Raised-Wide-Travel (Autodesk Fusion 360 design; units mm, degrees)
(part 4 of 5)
work_plane "WorkPlane10" AlongDistance -1.3 ExtraOffset 0
sketch "Upper clamp screw clearance" plane through (0, -1.3, 0) normal (0, 1, 0) x axis (1, 0, 0)
  circle C1 centre (44.5, -73) radius 1.7
extrude "Extrude10" cut sketch "Upper clamp screw clearance" along normal blind 6.4
work_plane "WorkPlane11" AlongDistance 5 ExtraOffset 0
sketch "Upper clamp head recess" plane through (0, 5, 0) normal (0, 1, 0) x axis (1, 0, 0)
  circle C1 centre (44.5, -73) radius 3.1
extrude "Extrude11" cut sketch "Upper clamp head recess" along normal blind 30
work_plane "WorkPlane1" AlongDistance -7 ExtraOffset 0
sketch "G01 upper clamp M3x12" plane through (0, -7, 0) normal (0, 1, 0) x axis (1, 0, 0)
  circle C1 centre (44.5, -73) radius 1.5
extrude "Extrude1" new body sketch "G01 upper clamp M3x12" along normal blind 12 bodies "HARDWARE G01 upper clamp M3x12"
work_plane "WorkPlane2" AlongDistance 5 ExtraOffset 0
sketch "Button head" plane through (0, 5, 0) normal (0, 1, 0) x axis (1, 0, 0)
  circle C1 centre (44.5, -73) radius 2.75
extrude "Extrude2" add sketch "Button head" along normal blind 3
ground "Unpin124"
ground "Unpin125"
ground "Unpin126"
ground "Unpin127"
ground "Unpin130"
ground "Unpin131"
ground "Unpin132"
ground "Unpin133"
ground "Unpin134"
ground "Unpin135"
ground "Unpin136"
ground "Unpin141"
ground "Unpin142"
ground "Unpin143"
ground "Unpin144"
ground "Unpin145"
ground "Unpin146"
ground "Unpin147"
ground "Unpin148"
ground "Unpin149"
ground "Unpin150"
ground "Unpin151"
ground "Unpin152"
position "Position2"
work_plane "WorkPlane86" AlongDistance 24 ExtraOffset 0
sketch "Outer lower sensor support clear of cam" plane through (24, 0, 0) normal (1, 0, 0) x axis (0, 0, -1)
  line L1 (-4, -49) -> (-4, -62)
  line L2 (-35, -49) -> (-4, -49)
  line L3 (-35, -62) -> (-35, -49)
  line L4 (-4, -62) -> (-35, -62)
extrude "Extrude86" add sketch "Outer lower sensor support clear of cam" along normal blind 10
work_plane "WorkPlane87" AlongDistance 24 ExtraOffset 0
sketch "Outer lower M3 insert" plane through (24, 0, 0) normal (1, 0, 0) x axis (0, 0, -1)
  circle C1 centre (-19.85, -55) radius 2
extrude "Extrude87" cut sketch "Outer lower M3 insert" along normal blind 6.8
work_plane "WorkPlane88" AlongDistance 30.7 ExtraOffset 0
sketch "Outer lower screw clearance" plane through (30.7, 0, 0) normal (1, 0, 0) x axis (0, 0, -1)
  circle C1 centre (-19.85, -55) radius 1.7
extrude "Extrude88" cut sketch "Outer lower screw clearance" along normal blind 3.4
work_plane "WorkPlane89" AlongDistance 24 ExtraOffset 0
sketch "Outer lower sensor support clear of cam (1)" plane through (24, 0, 0) normal (1, 0, 0) x axis (0, 0, -1)
  line L1 (-4, 62) -> (-4, 49)
  line L2 (-35, 62) -> (-4, 62)
  line L3 (-35, 49) -> (-35, 62)
  line L4 (-4, 49) -> (-35, 49)
extrude "Extrude89" add sketch "Outer lower sensor support clear of cam (1)" along normal blind 10
work_plane "WorkPlane90" AlongDistance 24 ExtraOffset 0
sketch "Outer lower M3 insert (1)" plane through (24, 0, 0) normal (1, 0, 0) x axis (0, 0, -1)
  circle C1 centre (-19.85, 55) radius 2
extrude "Extrude90" cut sketch "Outer lower M3 insert (1)" along normal blind 6.8
work_plane "WorkPlane91" AlongDistance 30.7 ExtraOffset 0
sketch "Outer lower screw clearance (1)" plane through (30.7, 0, 0) normal (1, 0, 0) x axis (0, 0, -1)
  circle C1 centre (-19.85, 55) radius 1.7
extrude "Extrude91" cut sketch "Outer lower screw clearance (1)" along normal blind 3.4
work_plane "WorkPlane92" AlongDistance 23.9 ExtraOffset 0
sketch "Potentiometer body and lead clearance (1)" plane through (23.9, 0, 0) normal (1, 0, 0) x axis (0, 0, -1)
  line L1 (-8.5, 8) -> (-8.5, -8)
  line L2 (-31.2, 8) -> (-8.5, 8)
  line L3 (-31.2, -8) -> (-31.2, 8)
  line L4 (-8.5, -8) -> (-31.2, -8)
extrude "Extrude92" cut sketch "Potentiometer body and lead clearance (1)" along normal blind 10.2
work_plane "WorkPlane1" AlongDistance 34 ExtraOffset 0
sketch "Flat lower sensor panel" plane through (34, 0, 0) normal (1, 0, 0) x axis (0, 0, -1)
  line L1 (-4, 62) -> (-4, -62)
  line L2 (-34, 62) -> (-4, 62)
  line L3 (-34, -62) -> (-34, 62)
  line L4 (-4, -62) -> (-34, -62)
extrude "Extrude1" new body sketch "Flat lower sensor panel" along normal blind 3 bodies "G03R Lower removable potentiometer panel"
work_plane "WorkPlane2" AlongDistance 33.9 ExtraOffset 0
sketch "Sensor bushing clearance" plane through (33.9, 0, 0) normal (1, 0, 0) x axis (0, 0, -1)
  circle C1 centre (-19.85, 0) radius 3.6
extrude "Extrude2" cut sketch "Sensor bushing clearance" along normal blind 3.2
work_plane "WorkPlane3" AlongDistance 33.9 ExtraOffset 0
sketch "Radial mesh adjustment slot" plane through (33.9, 0, 0) normal (1, 0, 0) x axis (0, 0, -1)
  line L1 (-16.95, -53.3) -> (-16.95, -56.7)
  line L2 (-22.75, -53.3) -> (-16.95, -53.3)
  line L3 (-22.75, -56.7) -> (-22.75, -53.3)
  line L4 (-16.95, -56.7) -> (-22.75, -56.7)
extrude "Extrude3" cut sketch "Radial mesh adjustment slot" along normal blind 3.2
work_plane "WorkPlane1" AlongDistance 25 ExtraOffset 0
sketch "Lower panel M3x12 -55" plane through (25, 0, 0) normal (1, 0, 0) x axis (0, 0, -1)
  circle C1 centre (-19.85, -55) radius 1.5
extrude "Extrude1" new body sketch "Lower panel M3x12 -55" along normal blind 12 bodies "HARDWARE Lower panel M3x12 -55"
work_plane "WorkPlane2" AlongDistance 37 ExtraOffset 0
sketch "Button head" plane through (37, 0, 0) normal (1, 0, 0) x axis (0, 0, -1)
  circle C1 centre (-19.85, -55) radius 2.75
extrude "Extrude2" add sketch "Button head" along normal blind 3
work_plane "WorkPlane4" AlongDistance 33.9 ExtraOffset 0
sketch "Radial mesh adjustment slot (1)" plane through (33.9, 0, 0) normal (1, 0, 0) x axis (0, 0, -1)
  line L1 (-16.95, 56.7) -> (-16.95, 53.3)
  line L2 (-22.75, 56.7) -> (-16.95, 56.7)
  line L3 (-22.75, 53.3) -> (-22.75, 56.7)
  line L4 (-16.95, 53.3) -> (-22.75, 53.3)
extrude "Extrude4" cut sketch "Radial mesh adjustment slot (1)" along normal blind 3.2
work_plane "WorkPlane1" AlongDistance 25 ExtraOffset 0
sketch "Lower panel M3x12 55" plane through (25, 0, 0) normal (1, 0, 0) x axis (0, 0, -1)
  circle C1 centre (-19.85, 55) radius 1.5
extrude "Extrude1" new body sketch "Lower panel M3x12 55" along normal blind 12 bodies "HARDWARE Lower panel M3x12 55"
work_plane "WorkPlane2" AlongDistance 37 ExtraOffset 0
sketch "Button head" plane through (37, 0, 0) normal (1, 0, 0) x axis (0, 0, -1)
  circle C1 centre (-19.85, 55) radius 2.75
extrude "Extrude2" add sketch "Button head" along normal blind 3
position "Position3"
work_plane "WorkPlane74" AlongDistance -36 ExtraOffset 0
sketch "Top rail hanging suspension arm" plane through (-36, 0, 0) normal (1, 0, 0) x axis (0, 0, -1)
  line L1 (-33, -74.5) -> (-33, -55)
  line L2 (-102, -74.5) -> (-33, -74.5)
  line L3 (-102, -95) -> (-102, -74.5)
  line L4 (-111, -95) -> (-102, -95)
  line L5 (-111, -65) -> (-111, -95)
  line L6 (-57, -55) -> (-111, -65)
  line L7 (-33, -55) -> (-57, -55)
work_plane "WorkPlane75" AlongDistance 101.9 ExtraOffset 0
sketch "Top-access M5 mounting clearance" plane through (0, 0, 101.9) normal (0, 0, 1) x axis (1, 0, 0)
  circle C1 centre (-30, -85) radius 2.7
work_plane "WorkPlane1" AlongDistance 97 ExtraOffset 0
sketch "Top hanging rail M5x14 (-30, -1)" plane through (0, 0, 97) normal (0, 0, 1) x axis (1, 0, 0)
  circle C1 centre (-30, -85) radius 2.5
extrude "Extrude1" new body sketch "Top hanging rail M5x14 (-30, -1)" along normal blind 14 bodies "HARDWARE Top hanging rail M5x14 (-30, -1)"
work_plane "WorkPlane2" AlongDistance 111 ExtraOffset 0
sketch "Button head" plane through (0, 0, 111) normal (0, 0, 1) x axis (1, 0, 0)
  circle C1 centre (-30, -85) radius 4.25
extrude "Extrude2" add sketch "Button head" along normal blind 5
work_plane "WorkPlane76" AlongDistance -36 ExtraOffset 0
sketch "Top rail hanging suspension arm (1)" plane through (-36, 0, 0) normal (1, 0, 0) x axis (0, 0, -1)
  line L1 (-33, 74.5) -> (-33, 55)
  line L2 (-102, 74.5) -> (-33, 74.5)
  line L3 (-102, 95) -> (-102, 74.5)
  line L4 (-111, 95) -> (-102, 95)
  line L5 (-111, 65) -> (-111, 95)
  line L6 (-57, 55) -> (-111, 65)
  line L7 (-33, 55) -> (-57, 55)
work_plane "WorkPlane77" AlongDistance 101.9 ExtraOffset 0
sketch "Top-access M5 mounting clearance (1)" plane through (0, 0, 101.9) normal (0, 0, 1) x axis (1, 0, 0)
  circle C1 centre (-30, 85) radius 2.7
work_plane "WorkPlane1" AlongDistance 97 ExtraOffset 0
sketch "Top hanging rail M5x14 (-30, 1)" plane through (0, 0, 97) normal (0, 0, 1) x axis (1, 0, 0)
  circle C1 centre (-30, 85) radius 2.5
extrude "Extrude1" new body sketch "Top hanging rail M5x14 (-30, 1)" along normal blind 14 bodies "HARDWARE Top hanging rail M5x14 (-30, 1)"
work_plane "WorkPlane2" AlongDistance 111 ExtraOffset 0
sketch "Button head" plane through (0, 0, 111) normal (0, 0, 1) x axis (1, 0, 0)
  circle C1 centre (-30, 85) radius 4.25
extrude "Extrude2" add sketch "Button head" along normal blind 5
work_plane "WorkPlane93" AlongDistance 24 ExtraOffset 0
sketch "Top rail hanging suspension arm" plane through (24, 0, 0) normal (1, 0, 0) x axis (0, 0, -1)
  line L1 (-33, -74.5) -> (-33, -55)
  line L2 (-102, -74.5) -> (-33, -74.5)
  line L3 (-102, -95) -> (-102, -74.5)
  line L4 (-111, -95) -> (-102, -95)
  line L5 (-111, -65) -> (-111, -95)
  line L6 (-57, -55) -> (-111, -65)
  line L7 (-33, -55) -> (-57, -55)
work_plane "WorkPlane94" AlongDistance 101.9 ExtraOffset 0
sketch "Top-access M5 mounting clearance" plane through (0, 0, 101.9) normal (0, 0, 1) x axis (1, 0, 0)
  circle C1 centre (30, -85) radius 2.7
work_plane "WorkPlane1" AlongDistance 97 ExtraOffset 0
sketch "Top hanging rail M5x14 (30, -1)" plane through (0, 0, 97) normal (0, 0, 1) x axis (1, 0, 0)
  circle C1 centre (30, -85) radius 2.5
extrude "Extrude1" new body sketch "Top hanging rail M5x14 (30, -1)" along normal blind 14 bodies "HARDWARE Top hanging rail M5x14 (30, -1)"
work_plane "WorkPlane2" AlongDistance 111 ExtraOffset 0
sketch "Button head" plane through (0, 0, 111) normal (0, 0, 1) x axis (1, 0, 0)
  circle C1 centre (30, -85) radius 4.25
extrude "Extrude2" add sketch "Button head" along normal blind 5
work_plane "WorkPlane95" AlongDistance 24 ExtraOffset 0
sketch "Top rail hanging suspension arm (1)" plane through (24, 0, 0) normal (1, 0, 0) x axis (0, 0, -1)
  line L1 (-33, 74.5) -> (-33, 55)
  line L2 (-102, 74.5) -> (-33, 74.5)
  line L3 (-102, 95) -> (-102, 74.5)
  line L4 (-111, 95) -> (-102, 95)
  line L5 (-111, 65) -> (-111, 95)
  line L6 (-57, 55) -> (-111, 65)
  line L7 (-33, 55) -> (-57, 55)
work_plane "WorkPlane96" AlongDistance 101.9 ExtraOffset 0
sketch "Top-access M5 mounting clearance (1)" plane through (0, 0, 101.9) normal (0, 0, 1) x axis (1, 0, 0)
  circle C1 centre (30, 85) radius 2.7
work_plane "WorkPlane1" AlongDistance 97 ExtraOffset 0
sketch "Top hanging rail M5x14 (30, 1)" plane through (0, 0, 97) normal (0, 0, 1) x axis (1, 0, 0)
  circle C1 centre (30, 85) radius 2.5
extrude "Extrude1" new body sketch "Top hanging rail M5x14 (30, 1)" along normal blind 14 bodies "HARDWARE Top hanging rail M5x14 (30, 1)"
work_plane "WorkPlane2" AlongDistance 111 ExtraOffset 0
sketch "Button head" plane through (0, 0, 111) normal (0, 0, 1) x axis (1, 0, 0)
  circle C1 centre (30, 85) radius 4.25
extrude "Extrude2" add sketch "Button head" along normal blind 5
work_plane "WorkPlane97" AlongDistance 34 ExtraOffset 0
sketch "Recess seat for removable lower sensor panel" plane through (34, 0, 0) normal (1, 0, 0) x axis (0, 0, -1)
  line L1 (-3.8, 62.2) -> (-3.8, -62.2)
  line L2 (-34.2, 62.2) -> (-3.8, 62.2)
  line L3 (-34.2, -62.2) -> (-34.2, 62.2)
  line L4 (-3.8, -62.2) -> (-34.2, -62.2)
extrude "Extrude97" cut sketch "Recess seat for removable lower sensor panel" along normal blind 2.1
position "Position4"
work_plane "WorkPlane78" AlongDistance -36.1 ExtraOffset 0
sketch "Preserve crossblock screw through suspension arm" plane through (-36.1, 0, 0) normal (1, 0, 0) x axis (0, 0, -1)
  circle C1 centre (-53.5, -62) radius 1.7
work_plane "WorkPlane79" AlongDistance -36.1 ExtraOffset 0
sketch "Preserve crossblock screw through suspension arm (1)" plane through (-36.1, 0, 0) normal (1, 0, 0) x axis (0, 0, -1)
  circle C1 centre (-53.5, -70) radius 1.7
work_plane "WorkPlane98" AlongDistance 23.9 ExtraOffset 0
sketch "Preserve crossblock screw through suspension arm" plane through (23.9, 0, 0) normal (1, 0, 0) x axis (0, 0, -1)
  circle C1 centre (-53.5, -62) radius 1.7
work_plane "WorkPlane99" AlongDistance 23.9 ExtraOffset 0
sketch "Preserve crossblock screw through suspension arm (1)" plane through (23.9, 0, 0) normal (1, 0, 0) x axis (0, 0, -1)
  circle C1 centre (-53.5, -70) radius 1.7
work_plane "WorkPlane80" AlongDistance -36 ExtraOffset 0
sketch "Shorter top rail hanger" plane through (-36, 0, 0) normal (1, 0, 0) x axis (0, 0, -1)
  line L1 (-33, -74.5) -> (-33, -55)
  line L2 (-90, -74.5) -> (-33, -74.5)
  line L3 (-90, -95) -> (-90, -74.5)
  line L4 (-99, -95) -> (-90, -95)
  line L5 (-99, -65) -> (-99, -95)
  line L6 (-57, -55) -> (-99, -65)
  line L7 (-33, -55) -> (-57, -55)
extrude "Extrude80" add sketch "Shorter top rail hanger" along normal blind 12
work_plane "WorkPlane81" AlongDistance 89.9 ExtraOffset 0
sketch "Rail M5 clearance" plane through (0, 0, 89.9) normal (0, 0, 1) x axis (1, 0, 0)
  circle C1 centre (-30, -85) radius 2.7
extrude "Extrude81" cut sketch "Rail M5 clearance" along normal blind 9.2
work_plane "WorkPlane82" AlongDistance -36 ExtraOffset 0
sketch "Shorter top rail hanger (1)" plane through (-36, 0, 0) normal (1, 0, 0) x axis (0, 0, -1)
  line L1 (-33, 74.5) -> (-33, 55)
  line L2 (-90, 74.5) -> (-33, 74.5)
  line L3 (-90, 95) -> (-90, 74.5)
  line L4 (-99, 95) -> (-90, 95)
  line L5 (-99, 65) -> (-99, 95)
  line L6 (-57, 55) -> (-99, 65)
  line L7 (-33, 55) -> (-57, 55)
extrude "Extrude82" add sketch "Shorter top rail hanger (1)" along normal blind 12
work_plane "WorkPlane83" AlongDistance 89.9 ExtraOffset 0
sketch "Rail M5 clearance (1)" plane through (0, 0, 89.9) normal (0, 0, 1) x axis (1, 0, 0)
  circle C1 centre (-30, 85) radius 2.7
extrude "Extrude83" cut sketch "Rail M5 clearance (1)" along normal blind 9.2
work_plane "WorkPlane84" AlongDistance -36.1 ExtraOffset 0
sketch "Restore crossblock passage" plane through (-36.1, 0, 0) normal (1, 0, 0) x axis (0, 0, -1)
  circle C1 centre (-53.5, -62) radius 1.7
extrude "Extrude84" cut sketch "Restore crossblock passage" along normal blind 12.2
work_plane "WorkPlane85" AlongDistance -36.1 ExtraOffset 0
sketch "Restore crossblock passage (1)" plane through (-36.1, 0, 0) normal (1, 0, 0) x axis (0, 0, -1)
  circle C1 centre (-53.5, -70) radius 1.7
extrude "Extrude85" cut sketch "Restore crossblock passage (1)" along normal blind 12.2
work_plane "WorkPlane100" AlongDistance 24 ExtraOffset 0
sketch "Shorter top rail hanger" plane through (24, 0, 0) normal (1, 0, 0) x axis (0, 0, -1)
  line L1 (-33, -74.5) -> (-33, -55)
  line L2 (-90, -74.5) -> (-33, -74.5)
  line L3 (-90, -95) -> (-90, -74.5)
  line L4 (-99, -95) -> (-90, -95)
  line L5 (-99, -65) -> (-99, -95)
  line L6 (-57, -55) -> (-99, -65)
  line L7 (-33, -55) -> (-57, -55)
extrude "Extrude100" add sketch "Shorter top rail hanger" along normal blind 12
work_plane "WorkPlane101" AlongDistance 89.9 ExtraOffset 0
sketch "Rail M5 clearance" plane through (0, 0, 89.9) normal (0, 0, 1) x axis (1, 0, 0)
  circle C1 centre (30, -85) radius 2.7
extrude "Extrude101" cut sketch "Rail M5 clearance" along normal blind 9.2
work_plane "WorkPlane102" AlongDistance 24 ExtraOffset 0
sketch "Shorter top rail hanger (1)" plane through (24, 0, 0) normal (1, 0, 0) x axis (0, 0, -1)
  line L1 (-33, 74.5) -> (-33, 55)
  line L2 (-90, 74.5) -> (-33, 74.5)
  line L3 (-90, 95) -> (-90, 74.5)
  line L4 (-99, 95) -> (-90, 95)
  line L5 (-99, 65) -> (-99, 95)
  line L6 (-57, 55) -> (-99, 65)
  line L7 (-33, 55) -> (-57, 55)
extrude "Extrude102" add sketch "Shorter top rail hanger (1)" along normal blind 12
work_plane "WorkPlane103" AlongDistance 89.9 ExtraOffset 0
sketch "Rail M5 clearance (1)" plane through (0, 0, 89.9) normal (0, 0, 1) x axis (1, 0, 0)
  circle C1 centre (30, 85) radius 2.7
extrude "Extrude103" cut sketch "Rail M5 clearance (1)" along normal blind 9.2
work_plane "WorkPlane104" AlongDistance 23.9 ExtraOffset 0
sketch "Restore crossblock passage" plane through (23.9, 0, 0) normal (1, 0, 0) x axis (0, 0, -1)
  circle C1 centre (-53.5, -62) radius 1.7
extrude "Extrude104" cut sketch "Restore crossblock passage" along normal blind 12.2
work_plane "WorkPlane105" AlongDistance 23.9 ExtraOffset 0
sketch "Restore crossblock passage (1)" plane through (23.9, 0, 0) normal (1, 0, 0) x axis (0, 0, -1)
  circle C1 centre (-53.5, -70) radius 1.7
extrude "Extrude105" cut sketch "Restore crossblock passage (1)" along normal blind 12.2
work_plane "WorkPlane86" AlongDistance -24 ExtraOffset 0
sketch "120 degree steel core stop" plane through (-24, 0, 0) normal (1, 0, 0) x axis (0, 0, -1)
  circle C1 centre (-74.8056, -35.677) radius 6
extrude "Extrude86" add sketch "120 degree steel core stop" along normal blind 15
work_plane "WorkPlane87" AlongDistance -36.1 ExtraOffset 0
sketch "M3 stop core bore" plane through (-36.1, 0, 0) normal (1, 0, 0) x axis (0, 0, -1)
  circle C1 centre (-74.8056, -35.677) radius 1.7
extrude "Extrude87" cut sketch "M3 stop core bore" along normal blind 27.2
work_plane "WorkPlane88" AlongDistance -17.5 ExtraOffset 0
sketch "M3 captive plain nut" plane through (-17.5, 0, 0) normal (1, 0, 0) x axis (0, 0, -1)
  line L1 (-77.6556, -34.0316) -> (-74.8056, -32.3861)
  line L2 (-77.6556, -37.3225) -> (-77.6556, -34.0316)
  line L3 (-74.8056, -38.9679) -> (-77.6556, -37.3225)
  line L4 (-71.9556, -37.3225) -> (-74.8056, -38.9679)
  line L5 (-71.9556, -34.0316) -> (-71.9556, -37.3225)
  line L6 (-74.8056, -32.3861) -> (-71.9556, -34.0316)
extrude "Extrude88" cut sketch "M3 captive plain nut" along normal blind 4.01
work_plane "WorkPlane89" AlongDistance -36.1 ExtraOffset 0
sketch "M3x20 stop head recess" plane through (-36.1, 0, 0) normal (1, 0, 0) x axis (0, 0, -1)
  circle C1 centre (-74.8056, -35.677) radius 3.1
extrude "Extrude89" cut sketch "M3x20 stop head recess" along normal blind 4.6
work_plane "WorkPlane1" AlongDistance -31.5 ExtraOffset 0
sketch "Stop M3x20 cap head -1" plane through (-31.5, 0, 0) normal (1, 0, 0) x axis (0, 0, -1)
  circle C1 centre (-74.8056, -35.677) radius 1.5
extrude "Extrude1" new body sketch "Stop M3x20 cap head -1" along normal blind 20 bodies "HARDWARE Stop M3x20 cap head -1"
work_plane "WorkPlane2" AlongDistance -34.5 ExtraOffset 0
sketch "Button head" plane through (-34.5, 0, 0) normal (1, 0, 0) x axis (0, 0, -1)
  circle C1 centre (-74.8056, -35.677) radius 2.75
extrude "Extrude2" add sketch "Button head" along normal blind 3
work_plane "WorkPlane1" AlongDistance -17.5 ExtraOffset 0
sketch "Stop M3 plain captive nut -1" plane through (-17.5, 0, 0) normal (1, 0, 0) x axis (0, 0, -1)
  line L1 (-77.5556, -34.0893) -> (-74.8056, -32.5016)
  line L2 (-77.5556, -37.2648) -> (-77.5556, -34.0893)
  line L3 (-74.8056, -38.8525) -> (-77.5556, -37.2648)
  line L4 (-72.0556, -37.2648) -> (-74.8056, -38.8525)
  line L5 (-72.0556, -34.0893) -> (-72.0556, -37.2648)
  line L6 (-74.8056, -32.5016) -> (-72.0556, -34.0893)
extrude "Extrude1" new body sketch "Stop M3 plain captive nut -1" along normal blind 2.4 bodies "HARDWARE Stop M3 plain captive nut -1"
work_plane "WorkPlane2" AlongDistance -17.6 ExtraOffset 0
sketch "Thread envelope" plane through (-17.6, 0, 0) normal (1, 0, 0) x axis (0, 0, -1)
  circle C1 centre (-74.8056, -35.677) radius 1.5
extrude "Extrude2" cut sketch "Thread envelope" along normal blind 2.6
work_plane "WorkPlane90" AlongDistance -24 ExtraOffset 0
sketch "120 degree steel core stop (1)" plane through (-24, 0, 0) normal (1, 0, 0) x axis (0, 0, -1)
  circle C1 centre (-74.8056, 35.677) radius 6
extrude "Extrude90" add sketch "120 degree steel core stop (1)" along normal blind 15
work_plane "WorkPlane91" AlongDistance -36.1 ExtraOffset 0
sketch "M3 stop core bore (1)" plane through (-36.1, 0, 0) normal (1, 0, 0) x axis (0, 0, -1)
  circle C1 centre (-74.8056, 35.677) radius 1.7
extrude "Extrude91" cut sketch "M3 stop core bore (1)" along normal blind 27.2
work_plane "WorkPlane92" AlongDistance -17.5 ExtraOffset 0
sketch "M3 captive plain nut (1)" plane through (-17.5, 0, 0) normal (1, 0, 0) x axis (0, 0, -1)
  line L1 (-77.6556, 37.3225) -> (-74.8056, 38.9679)
  line L2 (-77.6556, 34.0316) -> (-77.6556, 37.3225)
  line L3 (-74.8056, 32.3861) -> (-77.6556, 34.0316)
  line L4 (-71.9556, 34.0316) -> (-74.8056, 32.3861)
  line L5 (-71.9556, 37.3225) -> (-71.9556, 34.0316)
  line L6 (-74.8056, 38.9679) -> (-71.9556, 37.3225)
extrude "Extrude92" cut sketch "M3 captive plain nut (1)" along normal blind 4.01
work_plane "WorkPlane93" AlongDistance -36.1 ExtraOffset 0
sketch "M3x20 stop head recess (1)" plane through (-36.1, 0, 0) normal (1, 0, 0) x axis (0, 0, -1)
  circle C1 centre (-74.8056, 35.677) radius 3.1
extrude "Extrude93" cut sketch "M3x20 stop head recess (1)" along normal blind 4.6
work_plane "WorkPlane1" AlongDistance -31.5 ExtraOffset 0
sketch "Stop M3x20 cap head 1" plane through (-31.5, 0, 0) normal (1, 0, 0) x axis (0, 0, -1)
  circle C1 centre (-74.8056, 35.677) radius 1.5
extrude "Extrude1" new body sketch "Stop M3x20 cap head 1" along normal blind 20 bodies "HARDWARE Stop M3x20 cap head 1"
work_plane "WorkPlane2" AlongDistance -34.5 ExtraOffset 0
sketch "Button head" plane through (-34.5, 0, 0) normal (1, 0, 0) x axis (0, 0, -1)
  circle C1 centre (-74.8056, 35.677) radius 2.75
extrude "Extrude2" add sketch "Button head" along normal blind 3
work_plane "WorkPlane1" AlongDistance -17.5 ExtraOffset 0
sketch "Stop M3 plain captive nut 1" plane through (-17.5, 0, 0) normal (1, 0, 0) x axis (0, 0, -1)
  line L1 (-77.5556, 37.2648) -> (-74.8056, 38.8525)
  line L2 (-77.5556, 34.0893) -> (-77.5556, 37.2648)
  line L3 (-74.8056, 32.5016) -> (-77.5556, 34.0893)
  line L4 (-72.0556, 34.0893) -> (-74.8056, 32.5016)
  line L5 (-72.0556, 37.2648) -> (-72.0556, 34.0893)
  line L6 (-74.8056, 38.8525) -> (-72.0556, 37.2648)
extrude "Extrude1" new body sketch "Stop M3 plain captive nut 1" along normal blind 2.4 bodies "HARDWARE Stop M3 plain captive nut 1"
work_plane "WorkPlane2" AlongDistance -17.6 ExtraOffset 0
sketch "Thread envelope" plane through (-17.6, 0, 0) normal (1, 0, 0) x axis (0, 0, -1)
  circle C1 centre (-74.8056, 35.677) radius 1.5
extrude "Extrude2" cut sketch "Thread envelope" along normal blind 2.6
work_plane "WorkPlane1" AlongDistance 7 ExtraOffset 0
sketch "Roller compensated wide travel cam" plane through (7, 0, 0) normal (1, 0, 0) x axis (0, 0, -1)
  line L1 (-46.7858, 45.5639) -> (-46.9806, 45.5802)
  line L2 (-46.6024, 45.5464) -> (-46.7858, 45.5639)
  line L3 (-46.4304, 45.5278) -> (-46.6024, 45.5464)
  line L4 (-46.2696, 45.5078) -> (-46.4304, 45.5278)
  line L5 (-46.1199, 45.4865) -> (-46.2696, 45.5078)
  line L6 (-45.9808, 45.464) -> (-46.1199, 45.4865)
  line L7 (-45.8519, 45.4403) -> (-45.9808, 45.464)
  line L8 (-45.7328, 45.4155) -> (-45.8519, 45.4403)
  line L9 (-45.6227, 45.3897) -> (-45.7328, 45.4155)
  line L10 (-45.5208, 45.363) -> (-45.6227, 45.3897)
  line L11 (-45.4263, 45.3354) -> (-45.5208, 45.363)
  line L12 (-45.3379, 45.3069) -> (-45.4263, 45.3354)
  line L13 (-45.2547, 45.2772) -> (-45.3379, 45.3069)
  line L14 (-45.1753, 45.2462) -> (-45.2547, 45.2772)
  line L15 (-45.0985, 45.2134) -> (-45.1753, 45.2462)
  line L16 (-45.023, 45.1784) -> (-45.0985, 45.2134)
  line L17 (-44.9476, 45.1406) -> (-45.023, 45.1784)
  line L18 (-44.8711, 45.0992) -> (-44.9476, 45.1406)
  line L19 (-44.7923, 45.0536) -> (-44.8711, 45.0992)
  line L20 (-44.7102, 45.0028) -> (-44.7923, 45.0536)
  line L21 (-44.6241, 44.9462) -> (-44.7102, 45.0028)
  line L22 (-44.5331, 44.8829) -> (-44.6241, 44.9462)
  line L23 (-44.4367, 44.8122) -> (-44.5331, 44.8829)
  line L24 (-44.3343, 44.7335) -> (-44.4367, 44.8122)
  line L25 (-44.2256, 44.6462) -> (-44.3343, 44.7335)
  line L26 (-44.1102, 44.5498) -> (-44.2256, 44.6462)
  line L27 (-43.988, 44.4442) -> (-44.1102, 44.5498)
  line L28 (-43.8587, 44.329) -> (-43.988, 44.4442)
  line L29 (-43.7222, 44.2043) -> (-43.8587, 44.329)
  line L30 (-43.5783, 44.0701) -> (-43.7222, 44.2043)
  line L31 (-43.4268, 43.9266) -> (-43.5783, 44.0701)
  line L32 (-43.2677, 43.7741) -> (-43.4268, 43.9266)
  line L33 (-43.1006, 43.6131) -> (-43.2677, 43.7741)
  line L34 (-42.9255, 43.4439) -> (-43.1006, 43.6131)
  line L35 (-42.742, 43.2673) -> (-42.9255, 43.4439)
  line L36 (-42.55, 43.084) -> (-42.742, 43.2673)
  line L37 (-42.3493, 42.8946) -> (-42.55, 43.084)
  line L38 (-42.1396, 42.7) -> (-42.3493, 42.8946)
  line L39 (-41.9208, 42.5013) -> (-42.1396, 42.7)
  line L40 (-41.6928, 42.2994) -> (-41.9208, 42.5013)
  line L41 (-41.4556, 42.0954) -> (-41.6928, 42.2994)
  line L42 (-41.2093, 41.8904) -> (-41.4556, 42.0954)
  line L43 (-40.9541, 41.6856) -> (-41.2093, 41.8904)
  line L44 (-40.6904, 41.4823) -> (-40.9541, 41.6856)
  line L45 (-40.4188, 41.2816) -> (-40.6904, 41.4823)
  line L46 (-40.1398, 41.0847) -> (-40.4188, 41.2816)
  line L47 (-39.8545, 40.8926) -> (-40.1398, 41.0847)
  line L48 (-39.5639, 40.7063) -> (-39.8545, 40.8926)
  line L49 (-39.2691, 40.5267) -> (-39.5639, 40.7063)
  line L50 (-38.9713, 40.3545) -> (-39.2691, 40.5267)
  line L51 (-38.6721, 40.1902) -> (-38.9713, 40.3545)
  line L52 (-38.3727, 40.034) -> (-38.6721, 40.1902)
  line L53 (-38.0744, 39.8861) -> (-38.3727, 40.034)
  line L54 (-37.7787, 39.7466) -> (-38.0744, 39.8861)
  line L55 (-37.4868, 39.6151) -> (-37.7787, 39.7466)
  line L56 (-37.1999, 39.4914) -> (-37.4868, 39.6151)
  line L57 (-36.9189, 39.3751) -> (-37.1999, 39.4914)
  line L58 (-36.645, 39.2655) -> (-36.9189, 39.3751)
  line L59 (-36.3788, 39.1623) -> (-36.645, 39.2655)
  line L60 (-36.1212, 39.0647) -> (-36.3788, 39.1623)
  line L61 (-35.8727, 38.9722) -> (-36.1212, 39.0647)
  line L62 (-35.6338, 38.8843) -> (-35.8727, 38.9722)
  line L63 (-35.4051, 38.8004) -> (-35.6338, 38.8843)
  line L64 (-35.1869, 38.7201) -> (-35.4051, 38.8004)
  line L65 (-34.9795, 38.6429) -> (-35.1869, 38.7201)
  line L66 (-34.7831, 38.5685) -> (-34.9795, 38.6429)
  line L67 (-34.5979, 38.4966) -> (-34.7831, 38.5685)
  line L68 (-34.4239, 38.427) -> (-34.5979, 38.4966)
  line L69 (-34.2612, 38.3594) -> (-34.4239, 38.427)
  line L70 (-34.1096, 38.2939) -> (-34.2612, 38.3594)
  line L71 (-33.969, 38.2303) -> (-34.1096, 38.2939)
  line L72 (-33.8391, 38.1685) -> (-33.969, 38.2303)
  line L73 (-33.7195, 38.1085) -> (-33.8391, 38.1685)
  line L74 (-33.6097, 38.0503) -> (-33.7195, 38.1085)
  line L75 (-33.5091, 37.9937) -> (-33.6097, 38.0503)
  line L76 (-33.4168, 37.9387) -> (-33.5091, 37.9937)
  line L77 (-33.3321, 37.885) -> (-33.4168, 37.9387)
  line L78 (-33.2539, 37.8322) -> (-33.3321, 37.885)
  line L79 (-33.1812, 37.78) -> (-33.2539, 37.8322)
  line L80 (-33.1129, 37.7277) -> (-33.1812, 37.78)
  line L81 (-33.0479, 37.6747) -> (-33.1129, 37.7277)
  line L82 (-32.9851, 37.6202) -> (-33.0479, 37.6747)
  line L83 (-32.9235, 37.5633) -> (-32.9851, 37.6202)
  line L84 (-32.862, 37.503) -> (-32.9235, 37.5633)
  line L85 (-32.7998, 37.4383) -> (-32.862, 37.503)
  line L86 (-32.7362, 37.368) -> (-32.7998, 37.4383)
  line L87 (-32.6705, 37.2912) -> (-32.7362, 37.368)
  line L88 (-32.6022, 37.2069) -> (-32.6705, 37.2912)
  line L89 (-32.5308, 37.1142) -> (-32.6022, 37.2069)
  line L90 (-32.4562, 37.0123) -> (-32.5308, 37.1142)
  line L91 (-32.3779, 36.9005) -> (-32.4562, 37.0123)
  line L92 (-32.2959, 36.7783) -> (-32.3779, 36.9005)
  line L93 (-32.21, 36.6453) -> (-32.2959, 36.7783)
  line L94 (-32.1201, 36.5013) -> (-32.21, 36.6453)
  line L95 (-32.0261, 36.346) -> (-32.1201, 36.5013)
  line L96 (-31.9277, 36.1795) -> (-32.0261, 36.346)
  line L97 (-31.8248, 36.002) -> (-31.9277, 36.1795)
  line L98 (-31.7171, 35.8135) -> (-31.8248, 36.002)
  line L99 (-31.6045, 35.6144) -> (-31.7171, 35.8135)
  line L100 (-31.4864, 35.4052) -> (-31.6045, 35.6144)
  line L101 (-31.3627, 35.1863) -> (-31.4864, 35.4052)
  line L102 (-31.2328, 34.9582) -> (-31.3627, 35.1863)
  line L103 (-31.0963, 34.7217) -> (-31.2328, 34.9582)
  line L104 (-30.9529, 34.4775) -> (-31.0963, 34.7217)
  line L105 (-30.8021, 34.2264) -> (-30.9529, 34.4775)
  line L106 (-30.6435, 33.9694) -> (-30.8021, 34.2264)
  line L107 (-30.4767, 33.7074) -> (-30.6435, 33.9694)
  line L108 (-30.3015, 33.4416) -> (-30.4767, 33.7074)
  line L109 (-30.1178, 33.1731) -> (-30.3015, 33.4416)
  line L110 (-29.9254, 32.9032) -> (-30.1178, 33.1731)
  line L111 (-29.7247, 32.6331) -> (-29.9254, 32.9032)
  line L112 (-29.5158, 32.3642) -> (-29.7247, 32.6331)
  line L113 (-29.2992, 32.0978) -> (-29.5158, 32.3642)
  line L114 (-29.0756, 31.8351) -> (-29.2992, 32.0978)
  line L115 (-28.8458, 31.5773) -> (-29.0756, 31.8351)
  line L116 (-28.6108, 31.3255) -> (-28.8458, 31.5773)
  line L117 (-28.3718, 31.0805) -> (-28.6108, 31.3255)
  line L118 (-28.13, 30.8431) -> (-28.3718, 31.0805)
  line L119 (-27.8865, 30.6139) -> (-28.13, 30.8431)
  line L120 (-27.6427, 30.3933) -> (-27.8865, 30.6139)
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extrude "Extrude1" new body sketch "Roller compensated wide travel cam" along normal blind 8 bodies "P08 Cam 8 gates - 116 degree span"
work_plane "WorkPlane2" AlongDistance 6.9 ExtraOffset 0
sketch "Cam screw clearance" plane through (6.9, 0, 0) normal (1, 0, 0) x axis (0, 0, -1)
  circle C1 centre (-39.5442, 25.4558) radius 1.7
extrude "Extrude2" cut sketch "Cam screw clearance" along normal blind 8.2
work_plane "WorkPlane3" AlongDistance 12 ExtraOffset 0
sketch "Cam head recess" plane through (12, 0, 0) normal (1, 0, 0) x axis (0, 0, -1)
  circle C1 centre (-39.5442, 25.4558) radius 3.1
extrude "Extrude3" cut sketch "Cam head recess" along normal blind 3.1
work_plane "WorkPlane4" AlongDistance 6.9 ExtraOffset 0
sketch "Cam screw clearance (1)" plane through (6.9, 0, 0) normal (1, 0, 0) x axis (0, 0, -1)
  circle C1 centre (-29, 0) radius 1.7
extrude "Extrude4" cut sketch "Cam screw clearance (1)" along normal blind 8.2
work_plane "WorkPlane5" AlongDistance 12 ExtraOffset 0
sketch "Cam head recess (1)" plane through (12, 0, 0) normal (1, 0, 0) x axis (0, 0, -1)
  circle C1 centre (-29, 0) radius 3.1
extrude "Extrude5" cut sketch "Cam head recess (1)" along normal blind 3.1
work_plane "WorkPlane6" AlongDistance 6.9 ExtraOffset 0
sketch "Cam screw clearance (2)" plane through (6.9, 0, 0) normal (1, 0, 0) x axis (0, 0, -1)
  circle C1 centre (-39.5442, -25.4558) radius 1.7
extrude "Extrude6" cut sketch "Cam screw clearance (2)" along normal blind 8.2
work_plane "WorkPlane7" AlongDistance 12 ExtraOffset 0
sketch "Cam head recess (2)" plane through (12, 0, 0) normal (1, 0, 0) x axis (0, 0, -1)
  circle C1 centre (-39.5442, -25.4558) radius 3.1
extrude "Extrude7" cut sketch "Cam head recess (2)" along normal blind 3.1
work_plane "WorkPlane1" AlongDistance 7 ExtraOffset 0
sketch "Roller compensated wide travel cam" plane through (7, 0, 0) normal (1, 0, 0) x axis (0, 0, -1)
  line L1 (-47.2232, 45.9898) -> (-47.3676, 46.0185)
  line L2 (-47.0847, 45.9596) -> (-47.2232, 45.9898)
  line L3 (-46.9517, 45.9277) -> (-47.0847, 45.9596)
  line L4 (-46.8237, 45.8942) -> (-46.9517, 45.9277)
  line L5 (-46.7004, 45.859) -> (-46.8237, 45.8942)
  line L6 (-46.5811, 45.822) -> (-46.7004, 45.859)
  line L7 (-46.4652, 45.7832) -> (-46.5811, 45.822)
  line L8 (-46.3522, 45.7423) -> (-46.4652, 45.7832)
  line L9 (-46.2414, 45.6993) -> (-46.3522, 45.7423)
  line L10 (-46.1322, 45.6539) -> (-46.2414, 45.6993)
  line L11 (-46.024, 45.6058) -> (-46.1322, 45.6539)
  line L12 (-45.916, 45.5547) -> (-46.024, 45.6058)
  line L13 (-45.8078, 45.5004) -> (-45.916, 45.5547)
  line L14 (-45.6986, 45.4424) -> (-45.8078, 45.5004)
  line L15 (-45.5881, 45.3805) -> (-45.6986, 45.4424)
  line L16 (-45.4756, 45.3143) -> (-45.5881, 45.3805)
  line L17 (-45.3607, 45.2433) -> (-45.4756, 45.3143)
  line L18 (-45.2431, 45.1673) -> (-45.3607, 45.2433)
  line L19 (-45.1224, 45.0861) -> (-45.2431, 45.1673)
  line L20 (-44.9982, 44.9992) -> (-45.1224, 45.0861)
  line L21 (-44.8704, 44.9065) -> (-44.9982, 44.9992)
  line L22 (-44.7386, 44.8078) -> (-44.8704, 44.9065)
  line L23 (-44.6027, 44.7029) -> (-44.7386, 44.8078)
  line L24 (-44.4626, 44.5919) -> (-44.6027, 44.7029)
  line L25 (-44.318, 44.4746) -> (-44.4626, 44.5919)
  line L26 (-44.1688, 44.3511) -> (-44.318, 44.4746)
  line L27 (-44.0149, 44.2214) -> (-44.1688, 44.3511)
  line L28 (-43.8562, 44.0858) -> (-44.0149, 44.2214)
  line L29 (-43.6926, 43.9444) -> (-43.8562, 44.0858)
  line L30 (-43.524, 43.7975) -> (-43.6926, 43.9444)
  line L31 (-43.3501, 43.6453) -> (-43.524, 43.7975)
  line L32 (-43.171, 43.4882) -> (-43.3501, 43.6453)
  line L33 (-42.9865, 43.3266) -> (-43.171, 43.4882)
  line L34 (-42.7965, 43.1608) -> (-42.9865, 43.3266)
  line L35 (-42.601, 42.9913) -> (-42.7965, 43.1608)
  line L36 (-42.3997, 42.8187) -> (-42.601, 42.9913)
  line L37 (-42.1927, 42.6433) -> (-42.3997, 42.8187)
  line L38 (-41.98, 42.4659) -> (-42.1927, 42.6433)
  line L39 (-41.7616, 42.2869) -> (-41.98, 42.4659)
  line L40 (-41.5374, 42.107) -> (-41.7616, 42.2869)
  line L41 (-41.3077, 41.9267) -> (-41.5374, 42.107)
  line L42 (-41.0725, 41.7467) -> (-41.3077, 41.9267)
  line L43 (-40.8321, 41.5676) -> (-41.0725, 41.7467)
  line L44 (-40.5867, 41.39) -> (-40.8321, 41.5676)
  line L45 (-40.3368, 41.2146) -> (-40.5867, 41.39)
  line L46 (-40.0826, 41.0418) -> (-40.3368, 41.2146)
  line L47 (-39.8248, 40.8722) -> (-40.0826, 41.0418)
  line L48 (-39.5639, 40.7063) -> (-39.8248, 40.8722)
  line L49 (-39.3004, 40.5445) -> (-39.5639, 40.7063)
  line L50 (-39.0349, 40.3871) -> (-39.3004, 40.5445)
  line L51 (-38.7682, 40.2345) -> (-39.0349, 40.3871)
  line L52 (-38.501, 40.0867) -> (-38.7682, 40.2345)
  line L53 (-38.2339, 39.9441) -> (-38.501, 40.0867)
  line L54 (-37.9676, 39.8065) -> (-38.2339, 39.9441)
  line L55 (-37.7028, 39.674) -> (-37.9676, 39.8065)
  line L56 (-37.4402, 39.5466) -> (-37.7028, 39.674)
  line L57 (-37.1804, 39.424) -> (-37.4402, 39.5466)
  line L58 (-36.9239, 39.3061) -> (-37.1804, 39.424)
  line L59 (-36.6714, 39.1927) -> (-36.9239, 39.3061)
  line L60 (-36.4233, 39.0834) -> (-36.6714, 39.1927)
  line L61 (-36.1801, 38.9781) -> (-36.4233, 39.0834)
  line L62 (-35.9423, 38.8763) -> (-36.1801, 38.9781)
  line L63 (-35.71, 38.7779) -> (-35.9423, 38.8763)
  line L64 (-35.4838, 38.6825) -> (-35.71, 38.7779)
  line L65 (-35.2639, 38.5899) -> (-35.4838, 38.6825)
  line L66 (-35.0505, 38.4997) -> (-35.2639, 38.5899)
  line L67 (-34.8439, 38.4117) -> (-35.0505, 38.4997)
  line L68 (-34.6443, 38.3257) -> (-34.8439, 38.4117)
  line L69 (-34.4517, 38.2414) -> (-34.6443, 38.3257)
  line L70 (-34.2663, 38.1586) -> (-34.4517, 38.2414)
  line L71 (-34.0882, 38.0773) -> (-34.2663, 38.1586)
  line L72 (-33.9174, 37.9972) -> (-34.0882, 38.0773)
  line L73 (-33.7538, 37.9181) -> (-33.9174, 37.9972)
  line L74 (-33.5975, 37.8401) -> (-33.7538, 37.9181)
  line L75 (-33.4483, 37.763) -> (-33.5975, 37.8401)
  line L76 (-33.3061, 37.6867) -> (-33.4483, 37.763)
  line L77 (-33.1706, 37.611) -> (-33.3061, 37.6867)
  line L78 (-33.0417, 37.536) -> (-33.1706, 37.611)
  line L79 (-32.919, 37.4615) -> (-33.0417, 37.536)
  line L80 (-32.8022, 37.3873) -> (-32.919, 37.4615)
  line L81 (-32.6908, 37.3133) -> (-32.8022, 37.3873)
  line L82 (-32.5845, 37.2393) -> (-32.6908, 37.3133)
  line L83 (-32.4827, 37.165) -> (-32.5845, 37.2393)
  line L84 (-32.385, 37.0903) -> (-32.4827, 37.165)
  line L85 (-32.2909, 37.0147) -> (-32.385, 37.0903)
  line L86 (-32.1997, 36.9379) -> (-32.2909, 37.0147)
  line L87 (-32.111, 36.8595) -> (-32.1997, 36.9379)
  line L88 (-32.0242, 36.7791) -> (-32.111, 36.8595)
  line L89 (-31.9389, 36.6961) -> (-32.0242, 36.7791)
  line L90 (-31.8545, 36.6101) -> (-31.9389, 36.6961)
  line L91 (-31.7707, 36.5206) -> (-31.8545, 36.6101)
  line L92 (-31.6869, 36.427) -> (-31.7707, 36.5206)
  line L93 (-31.6028, 36.3289) -> (-31.6869, 36.427)
  line L94 (-31.5182, 36.2257) -> (-31.6028, 36.3289)
  line L95 (-31.4327, 36.117) -> (-31.5182, 36.2257)
  line L96 (-31.3461, 36.0024) -> (-31.4327, 36.117)
  line L97 (-31.2582, 35.8815) -> (-31.3461, 36.0024)
  line L98 (-31.1688, 35.754) -> (-31.2582, 35.8815)
  line L99 (-31.0777, 35.6196) -> (-31.1688, 35.754)
  line L100 (-30.9848, 35.478) -> (-31.0777, 35.6196)
  line L101 (-30.89, 35.3293) -> (-30.9848, 35.478)
  line L102 (-30.7931, 35.1732) -> (-30.89, 35.3293)
  line L103 (-30.694, 35.0097) -> (-30.7931, 35.1732)
  line L104 (-30.5926, 34.8389) -> (-30.694, 35.0097)
  line L105 (-30.4886, 34.6608) -> (-30.5926, 34.8389)
  line L106 (-30.382, 34.4756) -> (-30.4886, 34.6608)
  line L107 (-30.2724, 34.2834) -> (-30.382, 34.4756)
  line L108 (-30.1599, 34.0844) -> (-30.2724, 34.2834)
  line L109 (-30.044, 33.879) -> (-30.1599, 34.0844)
  line L110 (-29.9247, 33.6673) -> (-30.044, 33.879)
  line L111 (-29.8016, 33.4498) -> (-29.9247, 33.6673)
  line L112 (-29.6745, 33.2269) -> (-29.8016, 33.4498)
  line L113 (-29.5432, 32.999) -> (-29.6745, 33.2269)
  line L114 (-29.4075, 32.7664) -> (-29.5432, 32.999)
  line L115 (-29.2671, 32.5298) -> (-29.4075, 32.7664)
  line L116 (-29.1219, 32.2896) -> (-29.2671, 32.5298)
  line L117 (-28.9716, 32.0465) -> (-29.1219, 32.2896)
  line L118 (-28.8163, 31.801) -> (-28.9716, 32.0465)
  line L119 (-28.6557, 31.5537) -> (-28.8163, 31.801)
  line L120 (-28.4898, 31.3054) -> (-28.6557, 31.5537)
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extrude "Extrude1" new body sketch "Roller compensated wide travel cam" along normal blind 8 bodies "P08 Cam 7 gates - 116 degree span"
work_plane "WorkPlane2" AlongDistance 6.9 ExtraOffset 0
sketch "Cam screw clearance" plane through (6.9, 0, 0) normal (1, 0, 0) x axis (0, 0, -1)
  circle C1 centre (-39.5442, 25.4558) radius 1.7
extrude "Extrude2" cut sketch "Cam screw clearance" along normal blind 8.2
work_plane "WorkPlane3" AlongDistance 12 ExtraOffset 0
sketch "Cam head recess" plane through (12, 0, 0) normal (1, 0, 0) x axis (0, 0, -1)
  circle C1 centre (-39.5442, 25.4558) radius 3.1
extrude "Extrude3" cut sketch "Cam head recess" along normal blind 3.1
work_plane "WorkPlane4" AlongDistance 6.9 ExtraOffset 0
sketch "Cam screw clearance (1)" plane through (6.9, 0, 0) normal (1, 0, 0) x axis (0, 0, -1)
  circle C1 centre (-29, 0) radius 1.7
extrude "Extrude4" cut sketch "Cam screw clearance (1)" along normal blind 8.2
work_plane "WorkPlane5" AlongDistance 12 ExtraOffset 0
sketch "Cam head recess (1)" plane through (12, 0, 0) normal (1, 0, 0) x axis (0, 0, -1)
  circle C1 centre (-29, 0) radius 3.1
extrude "Extrude5" cut sketch "Cam head recess (1)" along normal blind 3.1
work_plane "WorkPlane6" AlongDistance 6.9 ExtraOffset 0
sketch "Cam screw clearance (2)" plane through (6.9, 0, 0) normal (1, 0, 0) x axis (0, 0, -1)
  circle C1 centre (-39.5442, -25.4558) radius 1.7
extrude "Extrude6" cut sketch "Cam screw clearance (2)" along normal blind 8.2
work_plane "WorkPlane7" AlongDistance 12 ExtraOffset 0
sketch "Cam head recess (2)" plane through (12, 0, 0) normal (1, 0, 0) x axis (0, 0, -1)
  circle C1 centre (-39.5442, -25.4558) radius 3.1
extrude "Extrude7" cut sketch "Cam head recess (2)" along normal blind 3.1
work_plane "WorkPlane1" AlongDistance 7 ExtraOffset 0
sketch "Roller compensated wide travel cam" plane through (7, 0, 0) normal (1, 0, 0) x axis (0, 0, -1)
  line L1 (-48.3375, 46.4002) -> (-48.4993, 46.476)
  line L2 (-48.1754, 46.322) -> (-48.3375, 46.4002)
  line L3 (-48.0129, 46.2414) -> (-48.1754, 46.322)
  line L4 (-47.8499, 46.1582) -> (-48.0129, 46.2414)
  line L5 (-47.6864, 46.0726) -> (-47.8499, 46.1582)
  line L6 (-47.5223, 45.9845) -> (-47.6864, 46.0726)
  line L7 (-47.3575, 45.8939) -> (-47.5223, 45.9845)
  line L8 (-47.1919, 45.8008) -> (-47.3575, 45.8939)
  line L9 (-47.0255, 45.7052) -> (-47.1919, 45.8008)
  line L10 (-46.8583, 45.6071) -> (-47.0255, 45.7052)
  line L11 (-46.6901, 45.5066) -> (-46.8583, 45.6071)
  line L12 (-46.5209, 45.4036) -> (-46.6901, 45.5066)
  line L13 (-46.3508, 45.2982) -> (-46.5209, 45.4036)
  line L14 (-46.1795, 45.1905) -> (-46.3508, 45.2982)
  line L15 (-46.0072, 45.0804) -> (-46.1795, 45.1905)
  line L16 (-45.8337, 44.9681) -> (-46.0072, 45.0804)
  line L17 (-45.659, 44.8535) -> (-45.8337, 44.9681)
  line L18 (-45.4831, 44.7368) -> (-45.659, 44.8535)
  line L19 (-45.3059, 44.618) -> (-45.4831, 44.7368)
  line L20 (-45.1274, 44.4972) -> (-45.3059, 44.618)
  line L21 (-44.9476, 44.3744) -> (-45.1274, 44.4972)
  line L22 (-44.7665, 44.2498) -> (-44.9476, 44.3744)
  line L23 (-44.584, 44.1234) -> (-44.7665, 44.2498)
  line L24 (-44.4001, 43.9953) -> (-44.584, 44.1234)
  line L25 (-44.2147, 43.8656) -> (-44.4001, 43.9953)
  line L26 (-44.0279, 43.7345) -> (-44.2147, 43.8656)
  line L27 (-43.8397, 43.602) -> (-44.0279, 43.7345)
  line L28 (-43.6499, 43.4683) -> (-43.8397, 43.602)
  line L29 (-43.4587, 43.3333) -> (-43.6499, 43.4683)
  line L30 (-43.266, 43.1974) -> (-43.4587, 43.3333)
  line L31 (-43.0719, 43.0605) -> (-43.266, 43.1974)
  line L32 (-42.8762, 42.9229) -> (-43.0719, 43.0605)
  line L33 (-42.679, 42.7845) -> (-42.8762, 42.9229)
  line L34 (-42.4804, 42.6456) -> (-42.679, 42.7845)
  line L35 (-42.2803, 42.5062) -> (-42.4804, 42.6456)
  line L36 (-42.0787, 42.3665) -> (-42.2803, 42.5062)
  line L37 (-41.8758, 42.2266) -> (-42.0787, 42.3665)
  line L38 (-41.6714, 42.0867) -> (-41.8758, 42.2266)
  line L39 (-41.4658, 41.9467) -> (-41.6714, 42.0867)
  line L40 (-41.2588, 41.8069) -> (-41.4658, 41.9467)
  line L41 (-41.0506, 41.6674) -> (-41.2588, 41.8069)
  line L42 (-40.8412, 41.5282) -> (-41.0506, 41.6674)
  line L43 (-40.6306, 41.3895) -> (-40.8412, 41.5282)
  line L44 (-40.4191, 41.2514) -> (-40.6306, 41.3895)
  line L45 (-40.2065, 41.1139) -> (-40.4191, 41.2514)
  line L46 (-39.9931, 40.9772) -> (-40.2065, 41.1139)
  line L47 (-39.7788, 40.8413) -> (-39.9931, 40.9772)
  line L48 (-39.5639, 40.7063) -> (-39.7788, 40.8413)
  line L49 (-39.3483, 40.5723) -> (-39.5639, 40.7063)
  line L50 (-39.1323, 40.4393) -> (-39.3483, 40.5723)
  line L51 (-38.9158, 40.3074) -> (-39.1323, 40.4393)
  line L52 (-38.6991, 40.1766) -> (-38.9158, 40.3074)
  line L53 (-38.4822, 40.047) -> (-38.6991, 40.1766)
  line L54 (-38.2652, 39.9186) -> (-38.4822, 40.047)
  line L55 (-38.0483, 39.7914) -> (-38.2652, 39.9186)
  line L56 (-37.8316, 39.6654) -> (-38.0483, 39.7914)
  line L57 (-37.6152, 39.5406) -> (-37.8316, 39.6654)
  line L58 (-37.3993, 39.4171) -> (-37.6152, 39.5406)
  line L59 (-37.1839, 39.2948) -> (-37.3993, 39.4171)
  line L60 (-36.9692, 39.1737) -> (-37.1839, 39.2948)
  line L61 (-36.7552, 39.0537) -> (-36.9692, 39.1737)
  line L62 (-36.5422, 38.9349) -> (-36.7552, 39.0537)
  line L63 (-36.3302, 38.8171) -> (-36.5422, 38.9349)
  line L64 (-36.1193, 38.7005) -> (-36.3302, 38.8171)
  line L65 (-35.9097, 38.5848) -> (-36.1193, 38.7005)
  line L66 (-35.7014, 38.4701) -> (-35.9097, 38.5848)
  line L67 (-35.4946, 38.3563) -> (-35.7014, 38.4701)
  line L68 (-35.2893, 38.2434) -> (-35.4946, 38.3563)
  line L69 (-35.0856, 38.1312) -> (-35.2893, 38.2434)
  line L70 (-34.8837, 38.0198) -> (-35.0856, 38.1312)
  line L71 (-34.6836, 37.909) -> (-34.8837, 38.0198)
  line L72 (-34.4855, 37.7988) -> (-34.6836, 37.909)
  line L73 (-34.2892, 37.6891) -> (-34.4855, 37.7988)
  line L74 (-34.0951, 37.5799) -> (-34.2892, 37.6891)
  line L75 (-33.9031, 37.4711) -> (-34.0951, 37.5799)
  line L76 (-33.7132, 37.3627) -> (-33.9031, 37.4711)
  line L77 (-33.5256, 37.2545) -> (-33.7132, 37.3627)
  line L78 (-33.3403, 37.1465) -> (-33.5256, 37.2545)
  line L79 (-33.1574, 37.0387) -> (-33.3403, 37.1465)
  line L80 (-32.9768, 36.931) -> (-33.1574, 37.0387)
  line L81 (-32.7987, 36.8233) -> (-32.9768, 36.931)
  line L82 (-32.6231, 36.7155) -> (-32.7987, 36.8233)
  line L83 (-32.45, 36.6077) -> (-32.6231, 36.7155)
  line L84 (-32.2794, 36.4998) -> (-32.45, 36.6077)
  line L85 (-32.1114, 36.3916) -> (-32.2794, 36.4998)
  line L86 (-31.9459, 36.2832) -> (-32.1114, 36.3916)
  line L87 (-31.7831, 36.1746) -> (-31.9459, 36.2832)
  line L88 (-31.6228, 36.0656) -> (-31.7831, 36.1746)
  line L89 (-31.465, 35.9562) -> (-31.6228, 36.0656)
  line L90 (-31.3099, 35.8463) -> (-31.465, 35.9562)
  line L91 (-31.1573, 35.736) -> (-31.3099, 35.8463)
  line L92 (-31.0072, 35.6251) -> (-31.1573, 35.736)
  line L93 (-30.8597, 35.5137) -> (-31.0072, 35.6251)
  line L94 (-30.7146, 35.4016) -> (-30.8597, 35.5137)
  line L95 (-30.5719, 35.2888) -> (-30.7146, 35.4016)
  line L96 (-30.4317, 35.1753) -> (-30.5719, 35.2888)
  line L97 (-30.2938, 35.061) -> (-30.4317, 35.1753)
  line L98 (-30.1583, 34.9458) -> (-30.2938, 35.061)
  line L99 (-30.0249, 34.8297) -> (-30.1583, 34.9458)
  line L100 (-29.8938, 34.7126) -> (-30.0249, 34.8297)
  line L101 (-29.7648, 34.5945) -> (-29.8938, 34.7126)
  line L102 (-29.6379, 34.4753) -> (-29.7648, 34.5945)
  line L103 (-29.5129, 34.3549) -> (-29.6379, 34.4753)
  line L104 (-29.3899, 34.2333) -> (-29.5129, 34.3549)
  line L105 (-29.2687, 34.1104) -> (-29.3899, 34.2333)
  line L106 (-29.1493, 33.986) -> (-29.2687, 34.1104)
  line L107 (-29.0316, 33.8602) -> (-29.1493, 33.986)
  line L108 (-28.9155, 33.7329) -> (-29.0316, 33.8602)
  line L109 (-28.8009, 33.6039) -> (-28.9155, 33.7329)
  line L110 (-28.6878, 33.4732) -> (-28.8009, 33.6039)
  line L111 (-28.5762, 33.3408) -> (-28.6878, 33.4732)
  line L112 (-28.4658, 33.2065) -> (-28.5762, 33.3408)
  line L113 (-28.3567, 33.0702) -> (-28.4658, 33.2065)
  line L114 (-28.2488, 32.932) -> (-28.3567, 33.0702)
  line L115 (-28.142, 32.7916) -> (-28.2488, 32.932)
  line L116 (-28.0362, 32.6491) -> (-28.142, 32.7916)
  line L117 (-27.9314, 32.5044) -> (-28.0362, 32.6491)
  line L118 (-27.8275, 32.3574) -> (-27.9314, 32.5044)
  line L119 (-27.7245, 32.2081) -> (-27.8275, 32.3574)
  line L120 (-27.6223, 32.0564) -> (-27.7245, 32.2081)
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extrude "Extrude1" new body sketch "Roller compensated wide travel cam" along normal blind 8 bodies "P08 Cam 5 gates - 116 degree span"
work_plane "WorkPlane2" AlongDistance 6.9 ExtraOffset 0
sketch "Cam screw clearance" plane through (6.9, 0, 0) normal (1, 0, 0) x axis (0, 0, -1)
  circle C1 centre (-39.5442, 25.4558) radius 1.7
extrude "Extrude2" cut sketch "Cam screw clearance" along normal blind 8.2
work_plane "WorkPlane3" AlongDistance 12 ExtraOffset 0
sketch "Cam head recess" plane through (12, 0, 0) normal (1, 0, 0) x axis (0, 0, -1)
  circle C1 centre (-39.5442, 25.4558) radius 3.1
extrude "Extrude3" cut sketch "Cam head recess" along normal blind 3.1
work_plane "WorkPlane4" AlongDistance 6.9 ExtraOffset 0
sketch "Cam screw clearance (1)" plane through (6.9, 0, 0) normal (1, 0, 0) x axis (0, 0, -1)
  circle C1 centre (-29, 0) radius 1.7
extrude "Extrude4" cut sketch "Cam screw clearance (1)" along normal blind 8.2
work_plane "WorkPlane5" AlongDistance 12 ExtraOffset 0
sketch "Cam head recess (1)" plane through (12, 0, 0) normal (1, 0, 0) x axis (0, 0, -1)
  circle C1 centre (-29, 0) radius 3.1
extrude "Extrude5" cut sketch "Cam head recess (1)" along normal blind 3.1
work_plane "WorkPlane6" AlongDistance 6.9 ExtraOffset 0
sketch "Cam screw clearance (2)" plane through (6.9, 0, 0) normal (1, 0, 0) x axis (0, 0, -1)
  circle C1 centre (-39.5442, -25.4558) radius 1.7
extrude "Extrude6" cut sketch "Cam screw clearance (2)" along normal blind 8.2
work_plane "WorkPlane7" AlongDistance 12 ExtraOffset 0
sketch "Cam head recess (2)" plane through (12, 0, 0) normal (1, 0, 0) x axis (0, 0, -1)
  circle C1 centre (-39.5442, -25.4558) radius 3.1
extrude "Extrude7" cut sketch "Cam head recess (2)" along normal blind 3.1
work_plane "WorkPlane1" AlongDistance 7 ExtraOffset 0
